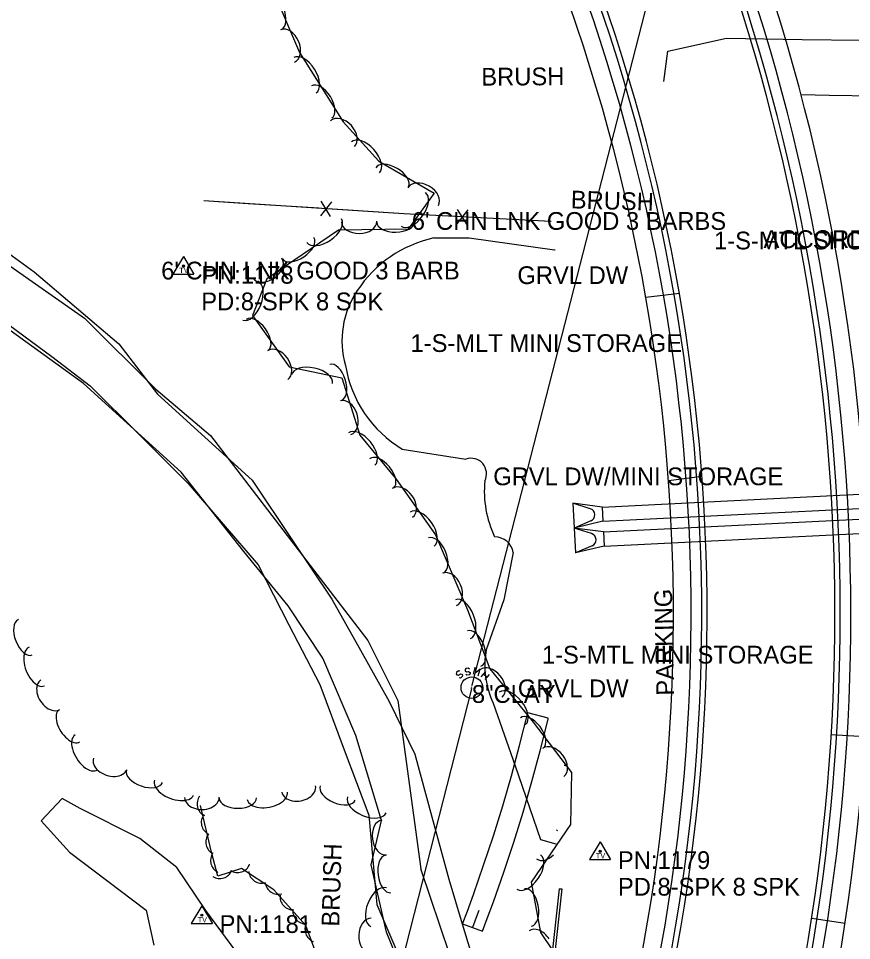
# Model space of a CAD drawing. Extents: x 978516 to 993312, y 1836504 to 1846212.
# Drawn here: x 992573.8 to 992808.5, y 1840853 to 1841112.7 of the extents above; entities that cross this region are included whole.
import ezdxf

# ---------------------------------------------------------------- set-up
doc = ezdxf.new("R2010")
doc.units = 0
for name, color, linetype in [('R_Drainage', 7, 'Continuous'), ('R_Proposed Road', 7, 'Continuous'), ('R_Special Ditch', 7, 'Continuous'), ('S_FENCE', 7, 'Continuous'), ('S_HIST_HIGH_WATER_ANNOT', 7, 'Continuous'), ('S_PARKING', 7, 'Continuous'), ('S_PARKING_ANNOT', 7, 'Continuous'), ('S_SANITARY_SEWER', 7, 'Continuous'), ('S_SANITARY_SEWER_ANNOT', 7, 'Continuous'), ('S_SECONDARY_CTL', 7, 'Continuous'), ('S_SECONDARY_CTL_ANNOT', 7, 'Continuous'), ('S_STREAM', 7, 'Continuous'), ('S_SURVEY_TEXT_ANNOT', 7, 'Continuous'), ('S_TREE', 7, 'Continuous'), ('S_TREE_ANNOT', 7, 'Continuous'), ('S_UTL_PT_SYM', 7, 'Continuous')]:
    doc.layers.add(name, color=color, linetype=linetype)

msp = doc.modelspace()

# ---------------------------------------------------------------- linework, layer by layer
at = {"layer": 'R_Drainage'}
for p, q in [((992738.24, 1840975.06), (992834.12, 1840979.84)), ((992730.01, 1840976.15), (992730.35, 1840969.16)), ((992738.24, 1840975.06), (992730.01, 1840976.15)), ((992734.9, 1840974.61), (992730.01, 1840976.15)), ((992738.24, 1840975.06), (992738.44, 1840971.07)), ((992738.44, 1840971.07), (992834.32, 1840975.85)), ((992738.59, 1840968.07), (992834.47, 1840972.85)), ((992735.07, 1840971.18), (992730.35, 1840969.16)), ((992738.44, 1840971.07), (992730.35, 1840969.16)), ((992730.35, 1840969.16), (992730.7, 1840962.17)), ((992738.59, 1840968.07), (992730.35, 1840969.16)), ((992735.25, 1840967.62), (992730.35, 1840969.16)), ((992738.59, 1840968.07), (992738.79, 1840964.07)), ((992738.79, 1840964.07), (992834.67, 1840968.86)), ((992735.42, 1840964.19), (992730.7, 1840962.17)), ((992738.79, 1840964.07), (992730.7, 1840962.17)), ((992723.06, 1840915.64), (992717.29, 1840917.09)), ((992726.11, 1840867.6), (992721.35, 1840822.85)), ((992726.85, 1840867.52), (992722.23, 1840823.99)), ((992726.11, 1840867.6), (992726.85, 1840867.52)), ((992698.93, 1840857.75), (992704.55, 1840855.66))]:
    msp.add_line(p, q, dxfattribs=at)
for points in [[(992698.93, 1840857.75), (992700.26, 1840861.3), (992701.95, 1840865.93), (992704.85, 1840874.19), (992707.61, 1840882.51), (992710.22, 1840890.9), (992712.68, 1840899.37), (992714.99, 1840907.91), (992717.29, 1840917.09)], [(992704.55, 1840855.66), (992705.89, 1840859.22), (992707.6, 1840863.91), (992710.52, 1840872.25), (992713.32, 1840880.67), (992715.97, 1840889.17), (992718.46, 1840897.75), (992720.8, 1840906.4), (992723.02, 1840915.3), (992723.06, 1840915.64)]]:
    msp.add_lwpolyline(points, dxfattribs=at)
for centre in [(992734.34, 1840972.87), (992734.69, 1840965.87)]:
    msp.add_arc(centre, 1.83, 293.1732, 72.536, dxfattribs=at)
at = {"layer": 'R_Proposed Road'}
for p, q in [((992760.01, 1841035.25), (992750.57, 1841034.08)), ((992766.4, 1840983.64), (992756.96, 1840982.47)), ((992802.83, 1840911.02), (992812.31, 1840910.45)), ((992797.33, 1840859.33), (992806.72, 1840857.89))]:
    msp.add_line(p, q, dxfattribs=at)
for radius, start, end in [(568.17, 348.1671, 28.1934), (573.17, 348.16715, 28.19343), (563.67, 348.1671, 28.1934), (565.17, 348.1671, 28.1934), (526.17, 344.9354, 28.1934), (527.67, 344.9354, 28.1934), (523.17, 344.9354, 28.1934), (518.17, 344.9354, 28.1934)]:
    msp.add_arc((992240.16, 1840944.72), radius, start, end, dxfattribs=at)
at = {"layer": 'R_Special Ditch'}
msp.add_lwpolyline([(992703.5, 1840861.44), (992703.07, 1840860.26), (992701.74, 1840856.7)], dxfattribs=at)
at = {"layer": 'S_FENCE'}
for p, q in [((992661.97, 1841061.04), (992658.85, 1841057.14)), ((992661.71, 1841056.95), (992659.11, 1841061.22)), ((992700.37, 1841058.75), (992697.29, 1841054.86)), ((992700.16, 1841054.71), (992697.51, 1841058.91))]:
    msp.add_line(p, q, dxfattribs=at)
for points in [[(992638.45, 1841060.5), (992626.05, 1841061.29)], [(992682.36, 1841057.68), (992626.05, 1841061.29)], [(992658.41, 1841059.22), (992638.45, 1841060.5)], [(992682.36, 1841057.68), (992662.4, 1841058.96)], [(992696.84, 1841056.91), (992682.36, 1841057.68)], [(992723.88, 1841055.47), (992723.82, 1841055.48), (992682.36, 1841057.68)]]:
    msp.add_lwpolyline(points, dxfattribs=at)
at = {"layer": 'S_PARKING'}
for points in [[(992725.04, 1841047.41), (992724.83, 1841047.41), (992700.75, 1841050.83), (992690.8, 1841050.85)], [(992681.92, 1840991.39), (992699.85, 1840988.56)], [(992713.2, 1840962.26), (992710.58, 1840948.92), (992705.6, 1840934.9)], [(992707.58, 1840919.81), (992713.74, 1840902.16), (992720.85, 1840881.46), (992725.17, 1840880.25)], [(992693.32, 1840708.4), (992691.13, 1840717.12), (992685.72, 1840730.85), (992674.81, 1840745.44), (992664.8, 1840761.65), (992657.37, 1840781.49), (992654.62, 1840813.13), (992647.97, 1840826.28), (992642.14, 1840840.31), (992626.56, 1840861.49), (992618.37, 1840873.61), (992607.99, 1840881.71), (992591.19, 1840890.16), (992586.07, 1840892.96), (992580.2, 1840886.7), (992588.13, 1840877.85), (992609.71, 1840861.55), (992611.96, 1840851.66)]]:
    msp.add_lwpolyline(points, dxfattribs=at)
for centre, radius, start, end in [((992698.23, 1841016.96), 34.7, 102.3785, 146.6761), ((992690.02, 1841021.97), 25.09, 145.9128, 196.1733), ((992699.26, 1841020.37), 33.77, 189.1813, 239.0992), ((992701.3, 1840984.44), 4.37, 332.8643, 109.2706), ((992734.93, 1840979.58), 29.89, 174.4981, 205.5139), ((992729.78, 1840930.4), 24.6, 169.4654, 205.4962)]:
    msp.add_arc(centre, radius, start, end, dxfattribs=at)
msp.add_ellipse((992707.91, 1840961.34), major_axis=(-2.65, 4.67), ratio=0.999772, start_param=4.368437, end_param=5.757314, dxfattribs=at)
at = {"layer": 'S_SANITARY_SEWER'}
for p, q in [((992751.11, 1841117.8), (992701.54, 1840924.93)), ((992697.21, 1840928.52), (992697.13, 1840928.14)), ((992697.13, 1840928.14), (992697.33, 1840927.86)), ((992697.75, 1840928.91), (992697.21, 1840928.52)), ((992697.33, 1840927.86), (992697.75, 1840927.75)), ((992698.18, 1840928.83), (992697.75, 1840928.91)), ((992697.75, 1840927.75), (992698.3, 1840928.1)), ((992698.3, 1840928.1), (992698.76, 1840928.02)), ((992698.76, 1840928.02), (992698.92, 1840927.75)), ((992698.92, 1840927.75), (992698.84, 1840927.32)), ((992704.19, 1840927.28), (992705.43, 1840928.76)), ((992704.84, 1840928.06), (992705.81, 1840927.24)), ((992706.39, 1840927.94), (992705.15, 1840926.47)), ((992698.3, 1840926.93), (992697.91, 1840927.01)), ((992698.84, 1840927.32), (992698.3, 1840926.93)), ((992701.4, 1840923.93), (992638.54, 1840677.41))]:
    msp.add_line(p, q, dxfattribs=at)
for points in [[(992700.85, 1840929.45), (992700.5, 1840929.72), (992699.85, 1840929.65), (992699.61, 1840929.3), (992699.65, 1840928.99), (992700, 1840928.68), (992700.62, 1840928.79), (992701.01, 1840928.48), (992701.05, 1840928.17), (992700.78, 1840927.79), (992700.16, 1840927.71), (992699.81, 1840927.98)], [(992703.29, 1840927.59), (992703.84, 1840929.45), (992702.79, 1840928.45), (992702.4, 1840929.88), (992701.86, 1840928.02)]]:
    msp.add_lwpolyline(points, dxfattribs=at)
msp.add_circle((992701.54, 1840924.22), 3.05, dxfattribs=at)
at = {"layer": 'S_SECONDARY_CTL'}
for p, q in [((992620.28, 1841045.6), (992617.27, 1841040.65)), ((992620.28, 1841045.6), (992623.23, 1841040.65)), ((992617.27, 1841040.65), (992623.23, 1841040.65)), ((992737.69, 1840880.76), (992734.68, 1840875.81)), ((992737.69, 1840880.76), (992740.63, 1840875.81)), ((992734.68, 1840875.81), (992740.63, 1840875.81)), ((992625.45, 1840862.75), (992622.44, 1840857.79)), ((992625.45, 1840862.75), (992628.4, 1840857.79)), ((992622.44, 1840857.79), (992628.4, 1840857.79))]:
    msp.add_line(p, q, dxfattribs=at)
for centre, radius in [((992620.28, 1841042.99), 0.311), ((992620.28, 1841042.99), 0.183), ((992620.28, 1841042.99), 0.103), ((992737.69, 1840878.15), 0.311), ((992737.69, 1840878.15), 0.183), ((992737.69, 1840878.15), 0.103), ((992625.45, 1840860.14), 0.311), ((992625.45, 1840860.14), 0.183), ((992625.45, 1840860.14), 0.103)]:
    msp.add_circle(centre, radius, dxfattribs=at)
at = {"layer": 'S_STREAM'}
for points in [[(992476.24, 1841164.01), (992491.82, 1841145.83), (992510.66, 1841122.48), (992527.6, 1841080.84), (992536.39, 1841068.14), (992548.35, 1841059.02), (992592.4, 1841028.3), (992612.52, 1841008.27), (992627.91, 1840995.24), (992656.87, 1840957.39), (992672.24, 1840937.52), (992680.65, 1840920.59), (992687.16, 1840873.15)], [(992696.55, 1840808.64), (992695.9, 1840810), (992677.45, 1840855.33), (992673.16, 1840874.34), (992676.08, 1840886.8), (992668.79, 1840910.71), (992659.5, 1840932.55), (992649.73, 1840947.27), (992637.26, 1840962.58), (992619.61, 1840984.91), (992592.11, 1841009.85), (992556.77, 1841035.29), (992521.03, 1841063.46), (992516.98, 1841070.42), (992500.42, 1841106.57), (992493.44, 1841124.55), (992482.9, 1841140.23)], [(992510.71, 1841078.33), (992524.18, 1841061.4), (992542.4, 1841047.95), (992553.75, 1841039.33), (992565.1, 1841030.7), (992583.21, 1841017.44), (992593.95, 1841009.24), (992607.75, 1840995.49), (992621.55, 1840981.73), (992631.45, 1840970.26), (992641.34, 1840958.78), (992650, 1840941.95), (992658.67, 1840925.13), (992665.59, 1840906.7), (992672.52, 1840888.28), (992673.61, 1840875.71), (992674.71, 1840863.14), (992680.36, 1840850.03), (992686.02, 1840836.91), (992691.67, 1840823.79), (992694.19, 1840817.95)], [(992524.46, 1841080.46), (992537.78, 1841067.59), (992547.62, 1841062.92), (992557.4, 1841056.39), (992567.77, 1841048.86), (992578.15, 1841041.32), (992590.08, 1841031.19), (992602.02, 1841021.06), (992612.97, 1841006.83), (992626.28, 1840994.73), (992639.59, 1840982.63), (992650.82, 1840965.9), (992662.05, 1840949.17), (992670.15, 1840934.75), (992678.24, 1840920.34), (992685.48, 1840905.46), (992690.26, 1840887.88), (992695.04, 1840870.3), (992698.84, 1840857.67), (992702.64, 1840845.04), (992706.22, 1840833.17)], [(992701.95, 1840832.61), (992698.09, 1840840.89), (992687.16, 1840873.15)]]:
    msp.add_lwpolyline(points, dxfattribs=at)
at = {"layer": 'S_TREE'}
for points in [[(992636.04, 1841135.11), (992644.61, 1841122.72), (992652.92, 1841103.14), (992665.23, 1841083.59), (992675.36, 1841072.53), (992690.87, 1841063.47), (992683.55, 1841053.3), (992663.92, 1841053.05), (992643.71, 1841039.38), (992639.75, 1841029.07), (992650.04, 1841014.58), (992664.9, 1841011.49), (992670.01, 1840995.31), (992680.16, 1840982.91), (992691.25, 1840967.28), (992700.28, 1840946.13), (992706.62, 1840929.53), (992718.85, 1840914.47), (992729.62, 1840900.3), (992729.33, 1840885.65), (992718.2, 1840869.47), (992720.86, 1840855.24), (992724.39, 1840850.07)], [(992755.65, 1841094.94), (992756.73, 1841103.46), (992773.26, 1841107.09), (992794.58, 1841106.71), (992811.04, 1841106.61), (992822.92, 1841106.58), (992837.55, 1841110.95), (992841.97, 1841101.1), (992857.15, 1841097.73), (992860.69, 1841090.58), (992866.85, 1841077.52), (992867.07, 1841061.76), (992857.45, 1841046.89), (992845.87, 1841043.65), (992838.78, 1841045.49), (992838.53, 1841055.93), (992838, 1841071.76), (992827.95, 1841090.61), (992802.2, 1841090.96), (992794.3, 1841091.2)], [(992722.72, 1840736.51), (992717.24, 1840736.8), (992704.2, 1840751.83), (992699.79, 1840770.07), (992694.88, 1840777.39), (992677.28, 1840794.81), (992665.92, 1840812.61), (992662.14, 1840837.15), (992654.79, 1840857.27), (992645.72, 1840867.31), (992636.66, 1840873.29), (992629.94, 1840871.13), (992628.15, 1840877.9), (992625.03, 1840891.07)]]:
    msp.add_lwpolyline(points, dxfattribs=at)
for centre, major_axis, ratio, start_param, end_param in [((992645.79, 1841114.51), (-2.09, 4.92), 0.538731, 3.141593, 6.283185), ((992649.58, 1841104.93), (-1.94, 4.56), 0.682816, 3.141593, 6.283185), ((992654.49, 1841096.67), (-3.13, 4.97), 0.548174, 3.141593, 6.283185), ((992659.22, 1841089.17), (-2.85, 4.52), 0.538827, 3.141593, 6.283185), ((992665.08, 1841080.23), (-3.35, 3.65), 0.683207, 3.141593, 6.283185), ((992671.53, 1841073.58), (-3.96, 4.33), 0.548391, 3.141593, 6.283185), ((992679.05, 1841067.93), (-4.62, 2.7), 0.539567, 3.141593, 6.283185), ((992687.81, 1841062.5), (-4.28, 2.5), 0.683875, 3.141593, 6.283185), ((992685, 1841058.94), (3.43, 4.76), 0.549399, 3.141593, 6.283185), ((992659.93, 1841052.92), (4.86, 3.29), 0.549939, 3.141593, 6.283185), ((992669.77, 1841055.51), (4.96, 0.06), 0.685069, 3.141593, 6.283185), ((992680.08, 1841055.38), (5.35, 0.07), 0.540508, 3.141593, 6.283185), ((992652.59, 1841047.95), (4.43, 3), 0.540561, 3.141593, 6.283185), ((992643.91, 1841042.39), (4.1, 2.78), 0.685135, 3.141593, 6.283185), ((992639.08, 1841033.22), (2.1, 5.48), 0.548887, 3.141593, 6.283185), ((992641.06, 1841023.58), (-3.1, 4.36), 0.538881, 3.141593, 6.283185), ((992646.81, 1841015.03), (-2.87, 4.04), 0.683006, 3.141593, 6.283185), ((992656.49, 1841011.07), (-5.75, 1.2), 0.549557, 3.141593, 6.283185), ((992663.1, 1841010.16), (-1.61, 5.1), 0.538721, 3.141593, 6.283185), ((992665.96, 1841000.26), (-1.49, 4.72), 0.682803, 3.141593, 6.283185), ((992670.48, 1840991.4), (-3.72, 4.54), 0.548313, 3.141593, 6.283185), ((992676.09, 1840984.54), (-3.39, 4.14), 0.538962, 3.141593, 6.283185), ((992681.97, 1840976.26), (-2.87, 4.04), 0.683006, 3.141593, 6.283185), ((992687.53, 1840968.86), (-3.4, 4.79), 0.548229, 3.141593, 6.283185), ((992691.44, 1840961.46), (-2.1, 4.92), 0.538732, 3.141593, 6.283185), ((992695.24, 1840951.88), (-1.95, 4.56), 0.682817, 3.141593, 6.283185), ((992699.02, 1840943.51), (-2.1, 5.48), 0.548069, 3.141593, 6.283185), ((992575.71, 1840938.41), (1.95, -4.98), 0.538726, 3.141419, 6.283011), ((992702.18, 1840935.23), (-1.91, 4.99), 0.538723, 3.141593, 6.283185), ((992578.94, 1840930.16), (2.14, -5.46), 0.548072, 3.141413, 6.283006), ((992706.92, 1840925.4), (-3.12, 3.85), 0.683103, 3.141593, 6.283185), ((992582.79, 1840922.27), (2.67, -4.18), 0.68299, 3.14281, 6.284403), ((992712.96, 1840918.37), (-3.7, 4.56), 0.548308, 3.141593, 6.283185), ((992588.12, 1840913.45), (2.88, -4.5), 0.538868, 3.142315, 6.283908), ((992718.45, 1840911.5), (-3.23, 4.26), 0.538917, 3.141593, 6.283185), ((992592.9, 1840905.98), (3.16, -4.94), 0.548217, 3.142338, 6.283931), ((992724.48, 1840903.14), (-3, 3.95), 0.683052, 3.141593, 6.283185), ((992599.59, 1840902.79), (4.69, -1.59), 0.684576, 3.143177, 6.28477), ((992727.43, 1840896.45), (0.11, 5.87), 0.548298, 5.986645, 6.283185), ((992609.27, 1840899.26), (5.06, -1.71), 0.54012, 3.142531, 6.284123), ((992617.61, 1840896.08), (5.46, -2.11), 0.55091, 3.144951, 6.286544), ((992652.75, 1840895.69), (4.76, 0.89), 0.70082, 3.145079, 6.286672), ((992663.73, 1840894.57), (4.95, -2.03), 0.539842, 3.141593, 6.283185), ((992643.9, 1840893.75), (5.64, 1.06), 0.56253, 3.143676, 6.285269), ((992625.47, 1840893.31), (4.88, 0.02), 0.695456, 3.147853, 6.289446), ((992627.69, 1840891.44), (0.84, -3.55), 0.977365, 3.825789, 5.598989), ((992635.62, 1840893.13), (5.27, 0.03), 0.54871, 3.145242, 6.286834), ((992671.94, 1840891.21), (5.43, -2.23), 0.549207, 3.141593, 6.283185), ((992628.85, 1840886.23), (0.84, -3.55), 0.977365, 3.825789, 5.598989), ((992676.84, 1840882.02), (0.67, -4.91), 0.682894, 3.141593, 6.283185), ((992722.6, 1840880.07), (2.81, 4.08), 0.684411, 6.148675, 6.283185), ((992630.12, 1840880.73), (0.84, -3.55), 0.977365, 3.825789, 5.598989), ((992631.44, 1840875.51), (0.93, -3.52), 0.977177, 3.825789, 5.598989), ((992677.97, 1840871.78), (0.72, -5.3), 0.538793, 3.141593, 6.283185), ((992717.57, 1840872.29), (3.33, 4.84), 0.549358, 3.141593, 6.283185), ((992722.6, 1840880.07), (2.81, 4.08), 0.684411, 3.141593, 4.451585), ((992635.51, 1840875.79), (3.47, 1.12), 0.999759, 3.825789, 5.598989), ((992630.5, 1840874.1), (3.47, 1.12), 0.999759, 3.825789, 5.598989), ((992642.2, 1840872.77), (1.39, -3.37), 0.976049, 4.432559, 6.20576), ((992646.86, 1840869.66), (1.39, -3.37), 0.976049, 4.432559, 6.20576), ((992675.25, 1840862.38), (-2.22, -5.43), 0.548931, 3.141593, 6.283185), ((992717.39, 1840862.3), (-0.98, 5.26), 0.53876, 3.141593, 6.283185), ((992651.08, 1840865.21), (2.43, -2.71), 0.97894, 3.828829, 5.60203), ((992654.66, 1840861.29), (2.43, -2.71), 0.97894, 3.828829, 5.60203), ((992658.04, 1840856.14), (0.37, -3.62), 0.975091, 4.081758, 5.854959), ((992673.02, 1840854.36), (-0.16, -4.95), 0.683111, 3.141593, 6.283185), ((992720.44, 1840851.65), (-2.8, 4.09), 0.682983, 4.695867, 6.283185)]:
    msp.add_ellipse(centre, major_axis=major_axis, ratio=ratio, start_param=start_param, end_param=end_param, dxfattribs=at)
at = {"layer": 'S_UTL_PT_SYM'}
for points in [[(992701.54, 1840924.93), (992701.54, 1840924.98), (992701.54, 1840924.93), (992701.49, 1840924.93), (992701.54, 1840924.93), (992701.54, 1840924.88), (992701.54, 1840924.93), (992701.59, 1840924.93)], [(992701.4, 1840923.93), (992701.4, 1840923.98), (992701.4, 1840923.93), (992701.35, 1840923.93), (992701.4, 1840923.93), (992701.4, 1840923.88), (992701.4, 1840923.93), (992701.45, 1840923.93)], [(992701.44, 1840924.38), (992701.44, 1840924.43), (992701.44, 1840924.38), (992701.39, 1840924.38), (992701.44, 1840924.38), (992701.44, 1840924.33), (992701.44, 1840924.38), (992701.49, 1840924.38)]]:
    msp.add_lwpolyline(points, dxfattribs=at)

# ---------------------------------------------------------------- texts
at = {"layer": 'S_HIST_HIGH_WATER_ANNOT'}
msp.add_text('ACCORDING TO PROPERTY OWNER ELEV:192.85', height=5, dxfattribs=at).set_placement((992783.73, 1841048.03))
at = {"layer": 'S_PARKING_ANNOT'}
msp.add_text('PARKING', height=5, rotation=91.2174, dxfattribs=at).set_placement((992758.55, 1840922.02))
at = {"layer": 'S_SANITARY_SEWER_ANNOT'}
msp.add_text('8"CLAY', height=5, dxfattribs=at).set_placement((992701.54, 1840919.93))
at = {"layer": 'S_SECONDARY_CTL'}
for p in [(992619.08, 1841040.98), (992736.48, 1840876.14), (992624.25, 1840858.13)]:
    msp.add_text('TV', height=1.5, dxfattribs=at).set_placement(p)
at = {"layer": 'S_SECONDARY_CTL_ANNOT'}
for s, p in [('PN:1178', (992625.28, 1841037.99)), ('PD:8-SPK 8 SPK', (992625.28, 1841030.49)), ('PN:1179', (992742.69, 1840873.15)), ('PD:8-SPK 8 SPK', (992742.69, 1840865.65)), ('PN:1181', (992630.45, 1840855.14))]:
    msp.add_text(s, height=5, dxfattribs=at).set_placement(p)
at = {"layer": 'S_SURVEY_TEXT_ANNOT'}
for s, p in [("6' CHN LNK GOOD 3 BARBS", (992684.6, 1841053.15)), ('1-S-MTL SHOP', (992769.78, 1841047.64)), ("6' CHN LNK GOOD 3 BARB", (992613.99, 1841039.18)), ('GRVL DW', (992714.37, 1841037.88)), ('1-S-MLT MINI STORAGE', (992684.24, 1841018.76)), ('GRVL DW/MINI STORAGE', (992707.56, 1840981.22)), ('1-S-MTL MINI STORAGE', (992721.28, 1840931)), ('GRVL DW', (992714.49, 1840921.53))]:
    msp.add_text(s, height=5, dxfattribs=at).set_placement(p)
at = {"layer": 'S_TREE_ANNOT'}
for rotation, p in [(0.3768, (992704.21, 1841093.75)), (358.2942, (992729.35, 1841059.21)), (88.2942, (992664.16, 1840856.87))]:
    msp.add_text('BRUSH', height=5, rotation=rotation, dxfattribs=at).set_placement(p)

doc.saveas('drawing.dxf')
